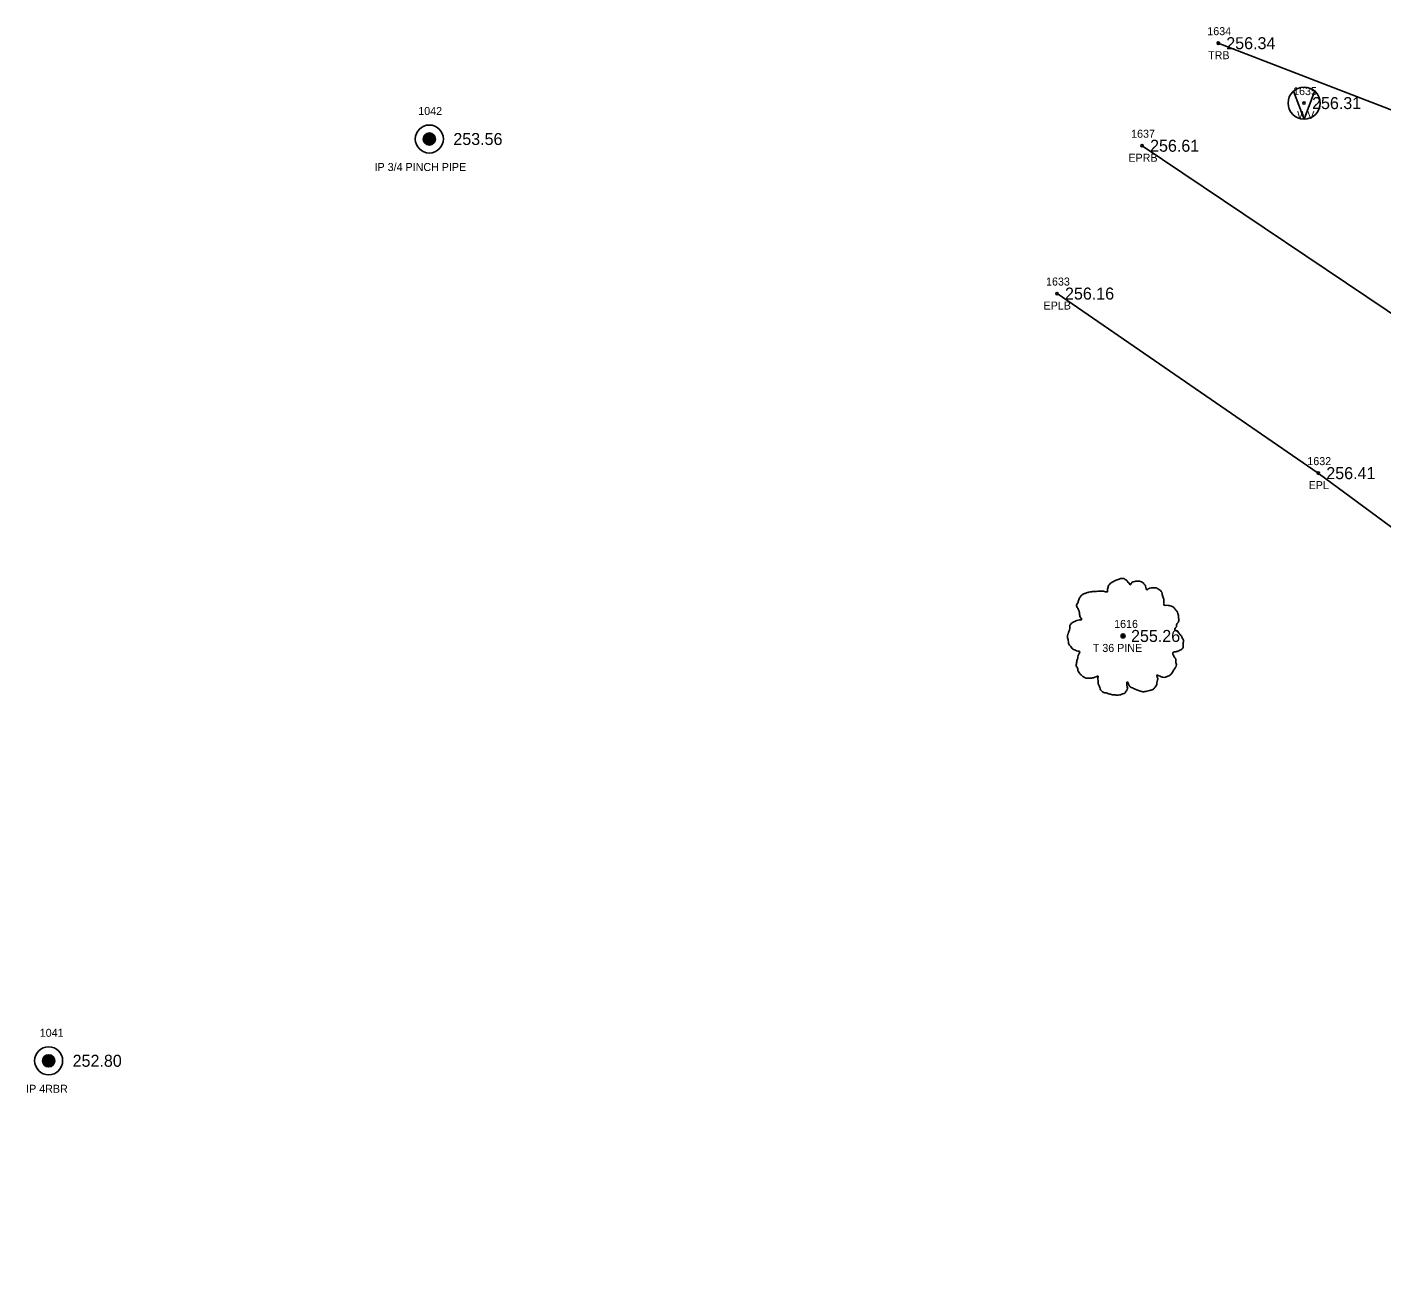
# Model space of a CAD drawing. Extents: x 1961231 to 1962574, y 799865 to 801120.
# Drawn here: x 1961231.4 to 1961400.7, y 800902.6 to 801060.1 of the extents above; entities that cross this region are included whole.
import ezdxf

# ---------------------------------------------------------------- set-up
doc = ezdxf.new("R2010")
doc.units = 0
for name, color, linetype in [('RD_EX_DV_Prop_txCode', 7, 'Continuous'), ('RD_EX_DV_PropPin', 7, 'Continuous'), ('RD_EX_Road', 7, 'Continuous'), ('RD_EX_Road_txCode', 7, 'Continuous'), ('RD_EX_TX_DV_Prop_ELEV', 7, 'Continuous'), ('RD_EX_TX_Road_ELEV', 7, 'Continuous'), ('RD_EX_TX_UT_ELEV', 7, 'Continuous'), ('RD_EX_TX_VEG_ELEV', 7, 'Continuous'), ('RD_EX_UT', 7, 'Continuous'), ('RD_EX_UT_txCode', 7, 'Continuous'), ('RD_EX_VEG', 7, 'Continuous'), ('RD_EX_VEG_txCode', 7, 'Continuous'), ('RD_SMD_Locator', 7, 'Continuous')]:
    doc.layers.add(name, color=color, linetype=linetype)

msp = doc.modelspace()

# ---------------------------------------------------------------- linework, layer by layer
at = {"layer": 'RD_EX_DV_PropPin'}
for p, q in [((1961280.9, 801045.9), (1961280.9, 801046.29)), ((1961280.93, 801045.8), (1961280.93, 801046.4)), ((1961280.97, 801045.73), (1961280.97, 801046.47)), ((1961281, 801045.67), (1961281, 801046.52)), ((1961281.04, 801045.62), (1961281.04, 801046.57)), ((1961281.07, 801045.58), (1961281.07, 801046.61)), ((1961281.11, 801045.55), (1961281.11, 801046.65)), ((1961281.14, 801045.52), (1961281.14, 801046.68)), ((1961281.18, 801045.49), (1961281.18, 801046.71)), ((1961281.21, 801045.46), (1961281.21, 801046.73)), ((1961281.25, 801045.44), (1961281.25, 801046.75)), ((1961281.28, 801045.42), (1961281.28, 801046.77)), ((1961281.32, 801045.4), (1961281.32, 801046.79)), ((1961281.35, 801045.39), (1961281.35, 801046.81)), ((1961281.39, 801045.38), (1961281.39, 801046.82)), ((1961281.42, 801045.37), (1961281.42, 801046.83)), ((1961281.46, 801045.36), (1961281.46, 801046.84)), ((1961281.49, 801045.35), (1961281.49, 801046.85)), ((1961281.53, 801045.34), (1961281.53, 801046.85)), ((1961281.56, 801045.34), (1961281.56, 801046.86)), ((1961281.6, 801045.34), (1961281.6, 801046.86)), ((1961281.63, 801045.34), (1961281.63, 801046.86)), ((1961281.67, 801045.34), (1961281.67, 801046.86)), ((1961281.7, 801045.34), (1961281.7, 801046.86)), ((1961281.74, 801045.34), (1961281.74, 801046.85)), ((1961281.77, 801045.35), (1961281.77, 801046.85)), ((1961281.81, 801045.36), (1961281.81, 801046.84)), ((1961281.84, 801045.37), (1961281.84, 801046.83)), ((1961281.88, 801045.38), (1961281.88, 801046.82)), ((1961281.91, 801045.39), (1961281.91, 801046.81)), ((1961281.95, 801045.4), (1961281.95, 801046.79)), ((1961281.98, 801045.42), (1961281.98, 801046.77)), ((1961282.02, 801045.44), (1961282.02, 801046.75)), ((1961282.05, 801045.46), (1961282.05, 801046.73)), ((1961282.09, 801045.49), (1961282.09, 801046.71)), ((1961282.12, 801045.52), (1961282.12, 801046.68)), ((1961282.16, 801045.55), (1961282.16, 801046.65)), ((1961282.19, 801045.58), (1961282.19, 801046.61)), ((1961282.23, 801045.62), (1961282.23, 801046.57)), ((1961282.26, 801045.67), (1961282.26, 801046.52)), ((1961282.3, 801045.73), (1961282.3, 801046.47)), ((1961282.33, 801045.8), (1961282.33, 801046.4)), ((1961282.37, 801045.9), (1961282.37, 801046.29)), ((1961233.32, 800930.68), (1961233.32, 800931.07)), ((1961233.36, 800930.58), (1961233.36, 800931.17)), ((1961233.39, 800930.51), (1961233.39, 800931.24)), ((1961233.43, 800930.45), (1961233.43, 800931.3)), ((1961233.46, 800930.4), (1961233.46, 800931.35)), ((1961233.5, 800930.36), (1961233.5, 800931.39)), ((1961233.53, 800930.32), (1961233.53, 800931.43)), ((1961233.57, 800930.29), (1961233.57, 800931.46)), ((1961233.6, 800930.26), (1961233.6, 800931.48)), ((1961233.64, 800930.24), (1961233.64, 800931.51)), ((1961233.67, 800930.22), (1961233.67, 800931.53)), ((1961233.71, 800930.2), (1961233.71, 800931.55)), ((1961233.74, 800930.18), (1961233.74, 800931.57)), ((1961233.78, 800930.17), (1961233.78, 800931.58)), ((1961233.81, 800930.15), (1961233.81, 800931.6)), ((1961233.85, 800930.14), (1961233.85, 800931.61)), ((1961233.88, 800930.13), (1961233.88, 800931.62)), ((1961233.92, 800930.13), (1961233.92, 800931.62)), ((1961233.95, 800930.12), (1961233.95, 800931.63)), ((1961233.99, 800930.12), (1961233.99, 800931.63)), ((1961234.02, 800930.11), (1961234.02, 800931.63)), ((1961234.06, 800930.11), (1961234.06, 800931.64)), ((1961234.09, 800930.11), (1961234.09, 800931.63)), ((1961234.13, 800930.12), (1961234.13, 800931.63)), ((1961234.16, 800930.12), (1961234.16, 800931.63)), ((1961234.2, 800930.13), (1961234.2, 800931.62)), ((1961234.23, 800930.13), (1961234.23, 800931.62)), ((1961234.27, 800930.14), (1961234.27, 800931.61)), ((1961234.3, 800930.15), (1961234.3, 800931.6)), ((1961234.34, 800930.17), (1961234.34, 800931.58)), ((1961234.37, 800930.18), (1961234.37, 800931.57)), ((1961234.41, 800930.2), (1961234.41, 800931.55)), ((1961234.44, 800930.22), (1961234.44, 800931.53)), ((1961234.48, 800930.24), (1961234.48, 800931.51)), ((1961234.51, 800930.26), (1961234.51, 800931.48)), ((1961234.55, 800930.29), (1961234.55, 800931.46)), ((1961234.58, 800930.32), (1961234.58, 800931.43)), ((1961234.62, 800930.36), (1961234.62, 800931.39)), ((1961234.65, 800930.4), (1961234.65, 800931.35)), ((1961234.69, 800930.45), (1961234.69, 800931.3)), ((1961234.72, 800930.51), (1961234.72, 800931.24)), ((1961234.76, 800930.58), (1961234.76, 800931.17)), ((1961234.79, 800930.68), (1961234.79, 800931.07))]:
    msp.add_line(p, q, dxfattribs=at)
for centre, radius in [((1961281.63, 801046.1), 1.75), ((1961281.63, 801046.1), 0.761), ((1961234.06, 800930.87), 1.75), ((1961234.06, 800930.87), 0.761)]:
    msp.add_circle(centre, radius, dxfattribs=at)
at = {"layer": 'RD_EX_Road'}
for points in [[(1961735.63, 800762.82), (1961702.92, 800788.52), (1961676.16, 800810.27), (1961651.45, 800830.73), (1961641.14, 800839.02), (1961595.18, 800874.45), (1961552.9, 800907.54), (1961510.92, 800940.49), (1961504.01, 800946.58), (1961476.53, 800968.16), (1961444.88, 800992.72), (1961406.41, 801021.23), (1961370.69, 801045.26)], [(1961722.95, 800745.11), (1961689.13, 800771.93), (1961670.14, 800787.03), (1961660.52, 800795.31), (1961637.49, 800813.67), (1961617.86, 800829), (1961581.48, 800857.91), (1961538.42, 800891.96), (1961505, 800917.96), (1961467.33, 800947.97), (1961432.02, 800975.33), (1961392.71, 801004.33), (1961360.06, 801026.78)]]:
    msp.add_lwpolyline(points, dxfattribs=at)
at = {"layer": 'RD_EX_UT'}
for q in [(1961389.62, 801052.08), (1961392.25, 801052.04)]:
    msp.add_line((1961390.93, 801048.6), q, dxfattribs=at)
msp.add_circle((1961390.93, 801050.59), 2, dxfattribs=at)
at = {"layer": 'RD_EX_VEG'}
msp.add_lwpolyline([(1961460.57, 801007.62), (1961418.99, 801043.13), (1961380.21, 801058.08)], dxfattribs=at)
for centre, radius in [((1961368.31, 800983.98), 0.25), ((1961368.3, 800983.96), 0.0001)]:
    msp.add_circle(centre, radius, dxfattribs=at)
for points in [[(1961368.45, 800991.15), (1961368.15, 800991.18), (1961367.82, 800991.08), (1961367.57, 800990.98), (1961367.35, 800990.9), (1961367.12, 800990.8), (1961366.82, 800990.63), (1961366.6, 800990.43), (1961366.47, 800990.18), (1961366.42, 800989.95), (1961366.37, 800989.68), (1961366.37, 800989.5), (1961366.25, 800989.48), (1961366.1, 800989.5), (1961365.85, 800989.58), (1961365.6, 800989.58), (1961365.35, 800989.58), (1961365, 800989.55), (1961364.65, 800989.55), (1961364.37, 800989.5), (1961364.05, 800989.45), (1961363.67, 800989.33), (1961363.32, 800989.2), (1961363.02, 800988.95), (1961362.77, 800988.48), (1961362.65, 800988.13), (1961362.5, 800987.88), (1961362.65, 800987.43), (1961362.82, 800987.08), (1961362.85, 800986.88), (1961362.92, 800986.45), (1961363.02, 800986.23), (1961363.15, 800986.03), (1961363.07, 800986), (1961362.7, 800985.95), (1961362.4, 800985.85), (1961361.97, 800985.63), (1961361.75, 800985.4), (1961361.65, 800985.08), (1961361.62, 800984.73), (1961361.52, 800984.53), (1961361.45, 800984.25), (1961361.42, 800984.18), (1961361.37, 800983.85), (1961361.47, 800983.4), (1961361.5, 800983.05), (1961361.62, 800982.83), (1961361.77, 800982.65), (1961361.95, 800982.4), (1961362.35, 800982.18), (1961362.67, 800982.08), (1961362.87, 800982.05), (1961362.7, 800981.55), (1961362.65, 800981.2), (1961362.52, 800980.8), (1961362.52, 800980.73), (1961362.47, 800980.26), (1961362.62, 800979.93), (1961362.7, 800979.56), (1961362.87, 800979.33), (1961363.15, 800979.03), (1961363.47, 800978.81), (1961363.97, 800978.68), (1961364.37, 800978.71), (1961364.95, 800978.88), (1961365.2, 800978.96), (1961365.17, 800978.78), (1961365.2, 800978.41), (1961365.2, 800977.98), (1961365.35, 800977.66), (1961365.45, 800977.38), (1961365.6, 800977.13), (1961365.92, 800976.91), (1961366.32, 800976.83), (1961366.75, 800976.68), (1961367.2, 800976.61), (1961367.7, 800976.58), (1961368.3, 800976.73), (1961368.57, 800976.86), (1961368.67, 800977.03), (1961368.87, 800977.41), (1961368.82, 800977.63), (1961368.85, 800978.23), (1961368.95, 800978.06), (1961369.12, 800977.71), (1961369.62, 800977.41), (1961370.02, 800977.23), (1961370.5, 800977.08), (1961370.8, 800977.01), (1961371.27, 800977.08), (1961371.65, 800977.16), (1961372.02, 800977.28), (1961372.32, 800977.56), (1961372.49, 800977.83), (1961372.54, 800978.11), (1961372.62, 800978.48), (1961372.67, 800978.66)], [(1961372.67, 800978.66), (1961372.59, 800978.83), (1961372.54, 800979.08), (1961372.62, 800979.06), (1961372.79, 800979.01), (1961373.07, 800978.88), (1961373.29, 800978.81), (1961373.62, 800978.83), (1961373.89, 800978.93), (1961374.34, 800979.21), (1961374.62, 800979.68), (1961374.89, 800980.08), (1961374.97, 800980.41), (1961374.92, 800980.63), (1961374.89, 800981.13), (1961374.69, 800981.38), (1961374.64, 800981.5), (1961374.54, 800981.9), (1961374.62, 800981.95), (1961374.89, 800982), (1961375.27, 800982.13), (1961375.54, 800982.25), (1961375.77, 800982.43), (1961375.84, 800982.65), (1961375.82, 800983.05), (1961375.87, 800983.45), (1961375.79, 800983.6), (1961375.69, 800983.75), (1961375.62, 800983.95), (1961375.47, 800984.1), (1961375.37, 800984.25), (1961375.27, 800984.35), (1961375.14, 800984.5), (1961374.97, 800984.63), (1961374.82, 800984.68), (1961374.77, 800984.83), (1961374.92, 800985.03), (1961374.97, 800985.13), (1961374.99, 800985.35), (1961375.22, 800985.7), (1961375.27, 800986.1), (1961375.22, 800986.53), (1961375.17, 800986.8), (1961375.02, 800987.08), (1961374.82, 800987.33), (1961374.69, 800987.5), (1961374.52, 800987.63), (1961374.19, 800987.75), (1961373.94, 800987.8), (1961373.59, 800987.8), (1961373.39, 800987.85), (1961373.42, 800987.9), (1961373.42, 800988.05), (1961373.42, 800988.33), (1961373.34, 800988.78), (1961373.19, 800989.28), (1961373.19, 800989.3), (1961373.09, 800989.55), (1961372.87, 800989.75), (1961372.69, 800989.85), (1961372.49, 800989.98), (1961372.24, 800990), (1961371.95, 800990), (1961371.67, 800989.95), (1961371.47, 800989.85), (1961371.3, 800989.73), (1961371.22, 800989.88), (1961371.12, 800990.18), (1961371.07, 800990.33), (1961370.92, 800990.5), (1961370.7, 800990.7), (1961370.25, 800990.83), (1961369.62, 800990.75), (1961369.32, 800990.55), (1961369.17, 800990.38), (1961369.12, 800990.5), (1961368.92, 800990.7), (1961368.82, 800990.88), (1961368.65, 800991), (1961368.5, 800991.1), (1961368.4, 800991.15)]]:
    msp.add_spline(points, degree=3, dxfattribs=at)
at = {"layer": 'RD_SMD_Locator'}
for centre in [(1961380.21, 801058.08), (1961390.93, 801050.59), (1961281.63, 801046.1), (1961370.69, 801045.26), (1961360.06, 801026.78), (1961392.71, 801004.33), (1961368.31, 800983.98), (1961234.06, 800930.87)]:
    msp.add_circle(centre, 0.15, dxfattribs=at)

# ---------------------------------------------------------------- texts
at = {"layer": 'RD_EX_DV_Prop_txCode'}
for s, p in [('1042', (1961280.25, 801049.1)), ('IP 3/4 PINCH PIPE', (1961274.79, 801042.1)), ('1041', (1961232.95, 800933.87)), ('IP 4RBR', (1961231.25, 800926.87))]:
    msp.add_text(s, height=1, dxfattribs=at).set_placement(p)
at = {"layer": 'RD_EX_Road_txCode'}
for s, p in [('1637', (1961369.32, 801046.26)), ('EPRB', (1961368.98, 801043.26)), ('1633', (1961358.69, 801027.78)), ('EPLB', (1961358.38, 801024.78)), ('1632', (1961391.34, 801005.33)), ('EPL', (1961391.5, 801002.33))]:
    msp.add_text(s, height=1, dxfattribs=at).set_placement(p)
at = {"layer": 'RD_EX_TX_DV_Prop_ELEV'}
for s, p in [('253.56', (1961284.63, 801045.35)), ('252.80', (1961237.06, 800930.12))]:
    msp.add_text(s, height=1.5, dxfattribs=at).set_placement(p)
at = {"layer": 'RD_EX_TX_Road_ELEV'}
for s, p in [('256.61', (1961371.69, 801044.51)), ('256.16', (1961361.06, 801026.03)), ('256.41', (1961393.71, 801003.58))]:
    msp.add_text(s, height=1.5, dxfattribs=at).set_placement(p)
at = {"layer": 'RD_EX_TX_UT_ELEV'}
msp.add_text('256.31', height=1.5, dxfattribs=at).set_placement((1961391.93, 801049.84))
at = {"layer": 'RD_EX_TX_VEG_ELEV'}
for s, p in [('256.34', (1961381.21, 801057.33)), ('255.26', (1961369.31, 800983.23))]:
    msp.add_text(s, height=1.5, dxfattribs=at).set_placement(p)
at = {"layer": 'RD_EX_UT_txCode'}
for s, p in [('1635', (1961389.56, 801051.59)), ('WV', (1961390.07, 801048.59))]:
    msp.add_text(s, height=1, dxfattribs=at).set_placement(p)
at = {"layer": 'RD_EX_VEG_txCode'}
for s, p in [('1634', (1961378.84, 801059.08)), ('TRB', (1961378.94, 801056.08)), ('1616', (1961367.2, 800984.98)), ('T 36 PINE', (1961364.53, 800981.98))]:
    msp.add_text(s, height=1, dxfattribs=at).set_placement(p)

doc.saveas('drawing.dxf')
